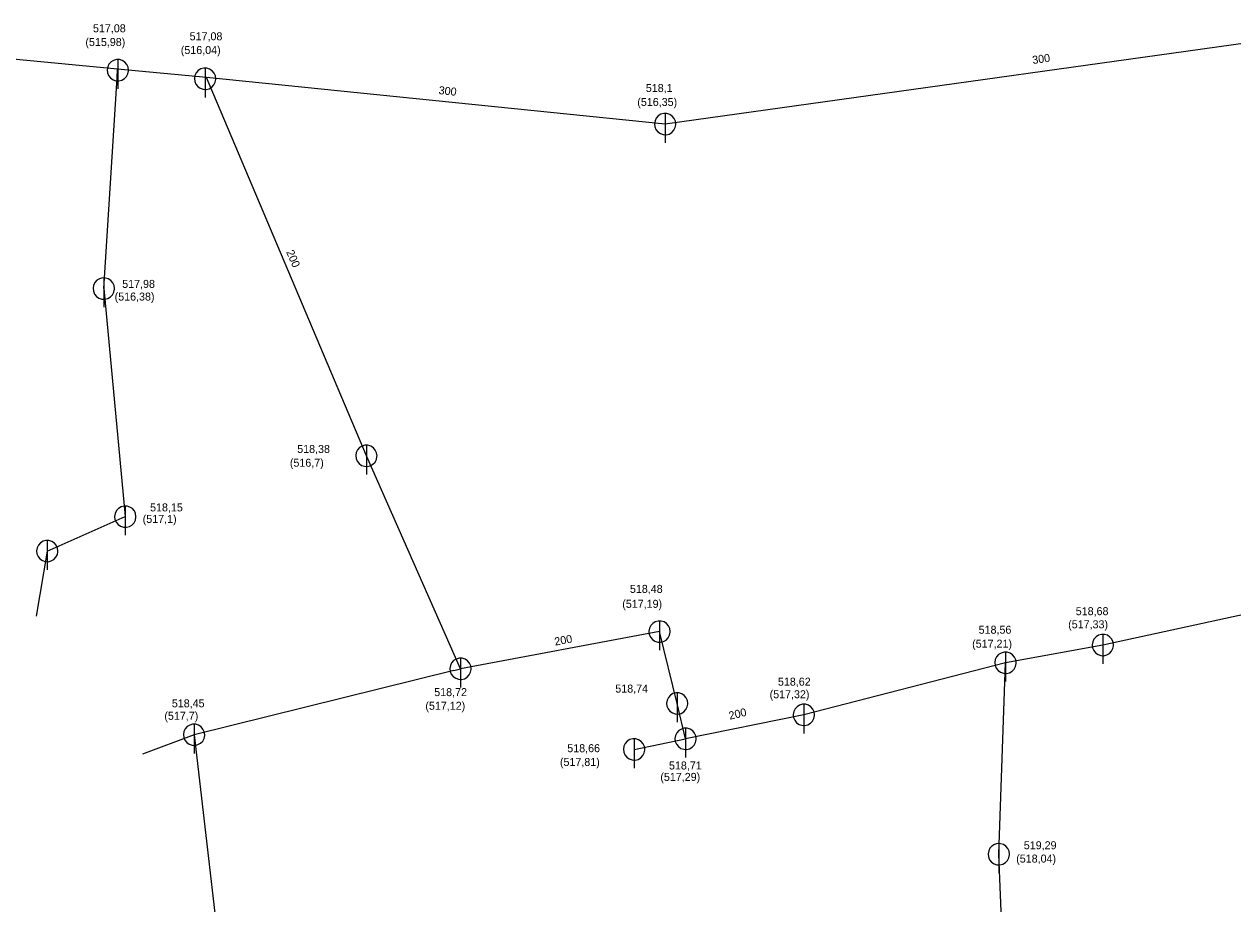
# Model space of a CAD drawing. Extents: x -476058 to -471893, y -1155786 to -1152000.
# Drawn here: x -473997.2 to -473883.9, y -1153989 to -1153906.5 of the extents above; entities that cross this region are included whole.
import ezdxf

# ---------------------------------------------------------------- set-up
doc = ezdxf.new("R2010")
doc.units = 0
for name, color, linetype in [('Vrstva 10', 7, 'Continuous'), ('Vrstva 18', 7, 'Continuous'), ('Vrstva 3', 7, 'Continuous'), ('Vrstva 4', 7, 'Continuous'), ('Vrstva 45', 7, 'Continuous'), ('Vrstva 50', 7, 'Continuous'), ('Vrstva 51', 7, 'Continuous')]:
    doc.layers.add(name, color=color, linetype=linetype)

msp = doc.modelspace()

# ---------------------------------------------------------------- linework, layer by layer
at = {"layer": 'Vrstva 10'}
for p, q in [((-473988.4, -1153909.83), (-473988.4, -1153912.58)), ((-473980.22, -1153910.64), (-473980.22, -1153913.39)), ((-473937.11, -1153914.89), (-473937.11, -1153917.64)), ((-473989.72, -1153930.31), (-473989.72, -1153933.06)), ((-473965.11, -1153946), (-473965.11, -1153948.75)), ((-473987.7, -1153951.7), (-473987.7, -1153954.45)), ((-473995.02, -1153954.93), (-473995.02, -1153957.68)), ((-473937.63, -1153962.48), (-473937.63, -1153965.23)), ((-473896.09, -1153963.74), (-473896.09, -1153966.49)), ((-473905.22, -1153965.41), (-473905.22, -1153968.16)), ((-473956.29, -1153965.97), (-473956.29, -1153968.72)), ((-473935.98, -1153969.22), (-473935.98, -1153971.97)), ((-473924.11, -1153970.29), (-473924.11, -1153973.04)), ((-473981.26, -1153972.16), (-473981.26, -1153974.9)), ((-473935.19, -1153972.54), (-473935.19, -1153975.29)), ((-473940.02, -1153973.53), (-473940.02, -1153976.28)), ((-473905.84, -1153983.35), (-473905.84, -1153986.1))]:
    msp.add_line(p, q, dxfattribs=at)
for points in [[(-473987.4, -1153910.83), (-473987.44, -1153910.55), (-473987.56, -1153910.3), (-473987.74, -1153910.08), (-473987.98, -1153909.93), (-473988.24, -1153909.84), (-473988.53, -1153909.84), (-473988.8, -1153909.92), (-473989.04, -1153910.06), (-473989.23, -1153910.27), (-473989.35, -1153910.53), (-473989.4, -1153910.8), (-473989.37, -1153911.08), (-473989.26, -1153911.34), (-473989.08, -1153911.56), (-473988.85, -1153911.73), (-473988.58, -1153911.82), (-473988.3, -1153911.83), (-473988.03, -1153911.76), (-473987.78, -1153911.62), (-473987.59, -1153911.42), (-473987.46, -1153911.17), (-473987.4, -1153910.89), (-473987.4, -1153910.83)], [(-473979.22, -1153911.64), (-473979.26, -1153911.36), (-473979.38, -1153911.1), (-473979.56, -1153910.89), (-473979.8, -1153910.73), (-473980.07, -1153910.65), (-473980.35, -1153910.65), (-473980.62, -1153910.72), (-473980.86, -1153910.87), (-473981.05, -1153911.08), (-473981.17, -1153911.33), (-473981.22, -1153911.61), (-473981.19, -1153911.89), (-473981.08, -1153912.15), (-473980.9, -1153912.37), (-473980.67, -1153912.53), (-473980.4, -1153912.62), (-473980.12, -1153912.64), (-473979.85, -1153912.57), (-473979.6, -1153912.43), (-473979.41, -1153912.22), (-473979.28, -1153911.97), (-473979.22, -1153911.7), (-473979.22, -1153911.64)], [(-473936.11, -1153915.89), (-473936.15, -1153915.61), (-473936.27, -1153915.35), (-473936.45, -1153915.14), (-473936.68, -1153914.99), (-473936.96, -1153914.9), (-473937.24, -1153914.9), (-473937.51, -1153914.97), (-473937.75, -1153915.12), (-473937.94, -1153915.33), (-473938.06, -1153915.58), (-473938.11, -1153915.86), (-473938.08, -1153916.14), (-473937.97, -1153916.4), (-473937.79, -1153916.62), (-473937.56, -1153916.78), (-473937.29, -1153916.87), (-473937.01, -1153916.89), (-473936.74, -1153916.82), (-473936.49, -1153916.68), (-473936.3, -1153916.47), (-473936.17, -1153916.22), (-473936.11, -1153915.95), (-473936.11, -1153915.89)], [(-473988.72, -1153931.31), (-473988.76, -1153931.03), (-473988.88, -1153930.78), (-473989.06, -1153930.56), (-473989.3, -1153930.41), (-473989.57, -1153930.33), (-473989.85, -1153930.32), (-473990.12, -1153930.4), (-473990.36, -1153930.54), (-473990.55, -1153930.75), (-473990.67, -1153931.01), (-473990.72, -1153931.29), (-473990.69, -1153931.57), (-473990.58, -1153931.83), (-473990.4, -1153932.05), (-473990.17, -1153932.21), (-473989.91, -1153932.3), (-473989.62, -1153932.31), (-473989.35, -1153932.24), (-473989.1, -1153932.1), (-473988.91, -1153931.9), (-473988.78, -1153931.65), (-473988.72, -1153931.37), (-473988.72, -1153931.31)], [(-473964.11, -1153947), (-473964.15, -1153946.72), (-473964.27, -1153946.46), (-473964.45, -1153946.25), (-473964.69, -1153946.09), (-473964.96, -1153946.01), (-473965.24, -1153946.01), (-473965.51, -1153946.08), (-473965.75, -1153946.23), (-473965.94, -1153946.44), (-473966.07, -1153946.69), (-473966.11, -1153946.97), (-473966.08, -1153947.25), (-473965.97, -1153947.51), (-473965.8, -1153947.73), (-473965.57, -1153947.89), (-473965.3, -1153947.98), (-473965.02, -1153948), (-473964.74, -1153947.93), (-473964.5, -1153947.79), (-473964.3, -1153947.58), (-473964.17, -1153947.33), (-473964.12, -1153947.06), (-473964.11, -1153947)], [(-473986.7, -1153952.7), (-473986.74, -1153952.42), (-473986.85, -1153952.17), (-473987.04, -1153951.95), (-473987.27, -1153951.8), (-473987.54, -1153951.72), (-473987.82, -1153951.71), (-473988.1, -1153951.79), (-473988.34, -1153951.93), (-473988.53, -1153952.14), (-473988.65, -1153952.4), (-473988.7, -1153952.68), (-473988.67, -1153952.96), (-473988.56, -1153953.22), (-473988.38, -1153953.44), (-473988.15, -1153953.6), (-473987.88, -1153953.69), (-473987.6, -1153953.7), (-473987.32, -1153953.63), (-473987.08, -1153953.49), (-473986.88, -1153953.29), (-473986.75, -1153953.04), (-473986.7, -1153952.76), (-473986.7, -1153952.7)], [(-473994.02, -1153955.93), (-473994.05, -1153955.65), (-473994.17, -1153955.39), (-473994.35, -1153955.18), (-473994.59, -1153955.03), (-473994.86, -1153954.94), (-473995.14, -1153954.94), (-473995.41, -1153955.01), (-473995.65, -1153955.16), (-473995.84, -1153955.37), (-473995.97, -1153955.62), (-473996.02, -1153955.9), (-473995.98, -1153956.18), (-473995.87, -1153956.44), (-473995.7, -1153956.66), (-473995.47, -1153956.82), (-473995.2, -1153956.91), (-473994.92, -1153956.93), (-473994.64, -1153956.86), (-473994.4, -1153956.72), (-473994.2, -1153956.51), (-473994.07, -1153956.26), (-473994.02, -1153955.99), (-473994.02, -1153955.93)], [(-473936.63, -1153963.48), (-473936.67, -1153963.2), (-473936.79, -1153962.94), (-473936.97, -1153962.73), (-473937.21, -1153962.57), (-473937.48, -1153962.49), (-473937.76, -1153962.49), (-473938.03, -1153962.56), (-473938.27, -1153962.71), (-473938.46, -1153962.92), (-473938.58, -1153963.17), (-473938.63, -1153963.45), (-473938.6, -1153963.73), (-473938.49, -1153963.99), (-473938.31, -1153964.21), (-473938.08, -1153964.37), (-473937.81, -1153964.46), (-473937.53, -1153964.48), (-473937.26, -1153964.41), (-473937.01, -1153964.27), (-473936.82, -1153964.06), (-473936.69, -1153963.81), (-473936.63, -1153963.54), (-473936.63, -1153963.48)], [(-473895.09, -1153964.74), (-473895.13, -1153964.46), (-473895.25, -1153964.2), (-473895.43, -1153963.99), (-473895.67, -1153963.83), (-473895.93, -1153963.75), (-473896.22, -1153963.75), (-473896.49, -1153963.82), (-473896.73, -1153963.97), (-473896.92, -1153964.18), (-473897.04, -1153964.43), (-473897.09, -1153964.71), (-473897.06, -1153964.99), (-473896.95, -1153965.25), (-473896.77, -1153965.47), (-473896.54, -1153965.63), (-473896.27, -1153965.72), (-473895.99, -1153965.74), (-473895.72, -1153965.67), (-473895.47, -1153965.53), (-473895.28, -1153965.32), (-473895.15, -1153965.07), (-473895.09, -1153964.8), (-473895.09, -1153964.74)], [(-473904.22, -1153966.41), (-473904.26, -1153966.13), (-473904.38, -1153965.87), (-473904.56, -1153965.66), (-473904.79, -1153965.51), (-473905.07, -1153965.42), (-473905.35, -1153965.42), (-473905.62, -1153965.49), (-473905.86, -1153965.64), (-473906.05, -1153965.85), (-473906.17, -1153966.1), (-473906.22, -1153966.38), (-473906.19, -1153966.66), (-473906.08, -1153966.92), (-473905.9, -1153967.14), (-473905.67, -1153967.3), (-473905.4, -1153967.39), (-473905.12, -1153967.41), (-473904.85, -1153967.34), (-473904.6, -1153967.2), (-473904.41, -1153966.99), (-473904.28, -1153966.74), (-473904.22, -1153966.47), (-473904.22, -1153966.41)], [(-473955.29, -1153966.97), (-473955.33, -1153966.69), (-473955.45, -1153966.43), (-473955.63, -1153966.22), (-473955.86, -1153966.06), (-473956.14, -1153965.98), (-473956.42, -1153965.98), (-473956.69, -1153966.05), (-473956.93, -1153966.2), (-473957.12, -1153966.41), (-473957.24, -1153966.66), (-473957.29, -1153966.94), (-473957.26, -1153967.22), (-473957.15, -1153967.48), (-473956.97, -1153967.7), (-473956.74, -1153967.86), (-473956.47, -1153967.95), (-473956.19, -1153967.97), (-473955.92, -1153967.9), (-473955.67, -1153967.76), (-473955.48, -1153967.55), (-473955.35, -1153967.3), (-473955.29, -1153967.03), (-473955.29, -1153966.97)], [(-473934.98, -1153970.22), (-473935.02, -1153969.94), (-473935.14, -1153969.68), (-473935.32, -1153969.47), (-473935.55, -1153969.31), (-473935.83, -1153969.23), (-473936.11, -1153969.23), (-473936.38, -1153969.3), (-473936.62, -1153969.45), (-473936.81, -1153969.66), (-473936.93, -1153969.91), (-473936.98, -1153970.19), (-473936.95, -1153970.47), (-473936.84, -1153970.73), (-473936.66, -1153970.95), (-473936.43, -1153971.11), (-473936.16, -1153971.2), (-473935.88, -1153971.22), (-473935.61, -1153971.15), (-473935.36, -1153971.01), (-473935.17, -1153970.8), (-473935.04, -1153970.55), (-473934.98, -1153970.28), (-473934.98, -1153970.22)], [(-473923.11, -1153971.29), (-473923.15, -1153971.01), (-473923.26, -1153970.75), (-473923.45, -1153970.54), (-473923.68, -1153970.38), (-473923.95, -1153970.3), (-473924.23, -1153970.3), (-473924.51, -1153970.37), (-473924.75, -1153970.52), (-473924.94, -1153970.73), (-473925.06, -1153970.98), (-473925.11, -1153971.26), (-473925.08, -1153971.54), (-473924.97, -1153971.8), (-473924.79, -1153972.02), (-473924.56, -1153972.18), (-473924.29, -1153972.27), (-473924.01, -1153972.28), (-473923.73, -1153972.22), (-473923.49, -1153972.07), (-473923.29, -1153971.87), (-473923.17, -1153971.62), (-473923.11, -1153971.34), (-473923.11, -1153971.29)], [(-473980.26, -1153973.16), (-473980.3, -1153972.88), (-473980.42, -1153972.62), (-473980.6, -1153972.4), (-473980.84, -1153972.25), (-473981.1, -1153972.17), (-473981.39, -1153972.16), (-473981.66, -1153972.24), (-473981.9, -1153972.39), (-473982.09, -1153972.59), (-473982.21, -1153972.85), (-473982.26, -1153973.13), (-473982.23, -1153973.41), (-473982.12, -1153973.67), (-473981.94, -1153973.89), (-473981.71, -1153974.05), (-473981.44, -1153974.14), (-473981.16, -1153974.15), (-473980.89, -1153974.08), (-473980.64, -1153973.94), (-473980.45, -1153973.74), (-473980.32, -1153973.49), (-473980.26, -1153973.21), (-473980.26, -1153973.16)], [(-473934.19, -1153973.54), (-473934.23, -1153973.26), (-473934.35, -1153973), (-473934.53, -1153972.79), (-473934.77, -1153972.64), (-473935.04, -1153972.55), (-473935.32, -1153972.55), (-473935.59, -1153972.62), (-473935.83, -1153972.77), (-473936.02, -1153972.98), (-473936.14, -1153973.23), (-473936.19, -1153973.51), (-473936.16, -1153973.79), (-473936.05, -1153974.05), (-473935.87, -1153974.27), (-473935.64, -1153974.43), (-473935.37, -1153974.52), (-473935.09, -1153974.54), (-473934.82, -1153974.47), (-473934.57, -1153974.33), (-473934.38, -1153974.12), (-473934.25, -1153973.87), (-473934.19, -1153973.6), (-473934.19, -1153973.54)], [(-473939.02, -1153974.53), (-473939.06, -1153974.25), (-473939.18, -1153973.99), (-473939.36, -1153973.78), (-473939.6, -1153973.62), (-473939.86, -1153973.54), (-473940.15, -1153973.54), (-473940.42, -1153973.61), (-473940.66, -1153973.76), (-473940.85, -1153973.97), (-473940.97, -1153974.22), (-473941.02, -1153974.5), (-473940.99, -1153974.78), (-473940.88, -1153975.04), (-473940.7, -1153975.26), (-473940.47, -1153975.42), (-473940.2, -1153975.51), (-473939.92, -1153975.53), (-473939.65, -1153975.46), (-473939.4, -1153975.32), (-473939.21, -1153975.11), (-473939.08, -1153974.86), (-473939.02, -1153974.59), (-473939.02, -1153974.53)], [(-473904.84, -1153984.35), (-473904.88, -1153984.08), (-473904.99, -1153983.82), (-473905.18, -1153983.6), (-473905.41, -1153983.45), (-473905.68, -1153983.37), (-473905.96, -1153983.36), (-473906.24, -1153983.44), (-473906.48, -1153983.59), (-473906.67, -1153983.79), (-473906.79, -1153984.05), (-473906.84, -1153984.33), (-473906.8, -1153984.61), (-473906.7, -1153984.87), (-473906.52, -1153985.09), (-473906.29, -1153985.25), (-473906.02, -1153985.34), (-473905.74, -1153985.35), (-473905.46, -1153985.28), (-473905.22, -1153985.14), (-473905.02, -1153984.94), (-473904.89, -1153984.69), (-473904.84, -1153984.41), (-473904.84, -1153984.35)]]:
    msp.add_lwpolyline(points, dxfattribs=at)
at = {"layer": 'Vrstva 45'}
for points in [[(-473988.42, -1153910.73), (-474021.48, -1153907.57)], [(-473870.42, -1153906.58), (-473937.11, -1153915.89)], [(-473980.1, -1153911.53), (-473988.42, -1153910.73)], [(-473937.11, -1153915.89), (-473980.1, -1153911.53)], [(-473965.11, -1153947), (-473980.1, -1153911.53)], [(-473956.29, -1153966.97), (-473965.11, -1153947)], [(-473871.23, -1153959.33), (-473896.09, -1153964.74)], [(-473937.63, -1153963.48), (-473956.29, -1153966.97)], [(-473935.98, -1153970.22), (-473937.63, -1153963.48)], [(-473896.09, -1153964.74), (-473905.22, -1153966.41)], [(-473905.22, -1153966.41), (-473924.11, -1153971.29)], [(-473905.84, -1153984.35), (-473905.22, -1153966.41)], [(-473935.19, -1153973.54), (-473935.98, -1153970.22)], [(-473924.11, -1153971.29), (-473935.19, -1153973.54)], [(-473940.02, -1153974.53), (-473935.19, -1153973.54)], [(-473905.32, -1153997.34), (-473905.84, -1153984.35)]]:
    msp.add_lwpolyline(points, dxfattribs=at)
at = {"layer": 'Vrstva 50'}
msp.add_line((-473989.72, -1153931.31), (-473987.7, -1153952.7), dxfattribs=at)
for points in [[(-473989.72, -1153931.31), (-473988.47, -1153911.56), (-473988.42, -1153910.73)], [(-473995.02, -1153955.93), (-473987.7, -1153952.7)], [(-473956.91, -1153967.12), (-473981.26, -1153973.16)], [(-473956.91, -1153967.12), (-473956.29, -1153966.97)], [(-473981.26, -1153973.16), (-473979.07, -1153992.05)]]:
    msp.add_lwpolyline(points, dxfattribs=at)
at = {"layer": 'Vrstva 51'}
for points in [[(-473995.02, -1153955.93), (-473996.04, -1153962.04)], [(-473981.26, -1153973.16), (-473986.08, -1153974.97)]]:
    msp.add_lwpolyline(points, dxfattribs=at)

# ---------------------------------------------------------------- texts
at = {"layer": 'Vrstva 18'}
for s, rotation, p in [('300 ', 7.9472, (-473902.65, -1153910.26)), ('300 ', 354.2064, (-473958.36, -1153913.07)), ('200 ', 293.3888, (-473972.64, -1153927.88)), ('200 ', 10.5937, (-473947.41, -1153964.8)), ('200 ', 13.3802, (-473931.05, -1153971.75))]:
    msp.add_text(s, height=0.75, rotation=rotation, dxfattribs=at).set_placement(p)
at = {"layer": 'Vrstva 3'}
for s, p in [('517,08', (-473990.73, -1153907.28)), ('517,08', (-473981.67, -1153908.03)), ('518,1', (-473938.92, -1153912.88)), ('517,98', (-473987.99, -1153931.25)), ('518,38', (-473971.59, -1153946.73)), ('518,15', (-473985.38, -1153952.21)), ('518,48', (-473940.41, -1153959.85)), ('518,68', (-473898.63, -1153961.94)), ('518,56', (-473907.73, -1153963.68)), ('518,72', (-473958.75, -1153969.53)), ('518,74', (-473941.78, -1153969.2)), ('518,62', (-473926.54, -1153968.55)), ('518,45', (-473983.34, -1153970.58)), ('518,66', (-473946.28, -1153974.79)), ('518,71', (-473936.75, -1153976.41)), ('519,29', (-473903.5, -1153983.89))]:
    msp.add_text(s, height=0.75, dxfattribs=at).set_placement(p)
at = {"layer": 'Vrstva 4'}
for s, p in [('(515,98)', (-473991.44, -1153908.57)), ('(516,04)', (-473982.5, -1153909.32)), ('(516,35)', (-473939.72, -1153914.19)), ('(516,38)', (-473988.7, -1153932.44)), ('(516,7)', (-473972.28, -1153948.02)), ('(517,1)', (-473986.07, -1153953.29)), ('(517,19)', (-473941.13, -1153961.25)), ('(517,33)', (-473899.34, -1153963.17)), ('(517,21)', (-473908.34, -1153964.99)), ('(517,32)', (-473927.32, -1153969.73)), ('(517,7)', (-473984.04, -1153971.75)), ('(517,12)', (-473959.58, -1153970.81)), ('(517,81)', (-473946.97, -1153976.08)), ('(517,29)', (-473937.56, -1153977.48)), ('(518,04)', (-473904.21, -1153985.14))]:
    msp.add_text(s, height=0.75, dxfattribs=at).set_placement(p)

doc.saveas('drawing.dxf')
